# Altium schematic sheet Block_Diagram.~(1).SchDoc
size 431 x 279 mm; Date: Not shown in title block; ApprovedBy: Not shown in title block; CheckedBy: Not shown in title block; Author: Not shown in title block; CompanyName: Not shown in title block; Engineer: Not shown in title block; Organization: Not shown in title block; Address1: Not shown in title block; Address2: Not shown in title block; Address3: Not shown in title block; Address4: Not shown in title block; DocumentNumber: 1; Revision: Use project parameter SCH_Rev; SheetNumber: 1; SheetTotal: 4; PageSetup: Record=PageOptions¦CenterHorizontal=True¦CenterVertical=True¦PrintScale=1.00¦XCorrection=1.00¦YCorrection=1.00¦PrintKind=0¦BorderSize=5000000¦LeftOffset=0¦BottomOffset=0¦Orientation=2¦PaperLength=1000¦PaperWidth=1000¦Scale=100¦PaperSource=15¦PrintQuality=600¦MediaType=1¦DitherType=10¦PaperKind=Letter¦PrintScaleMode=1
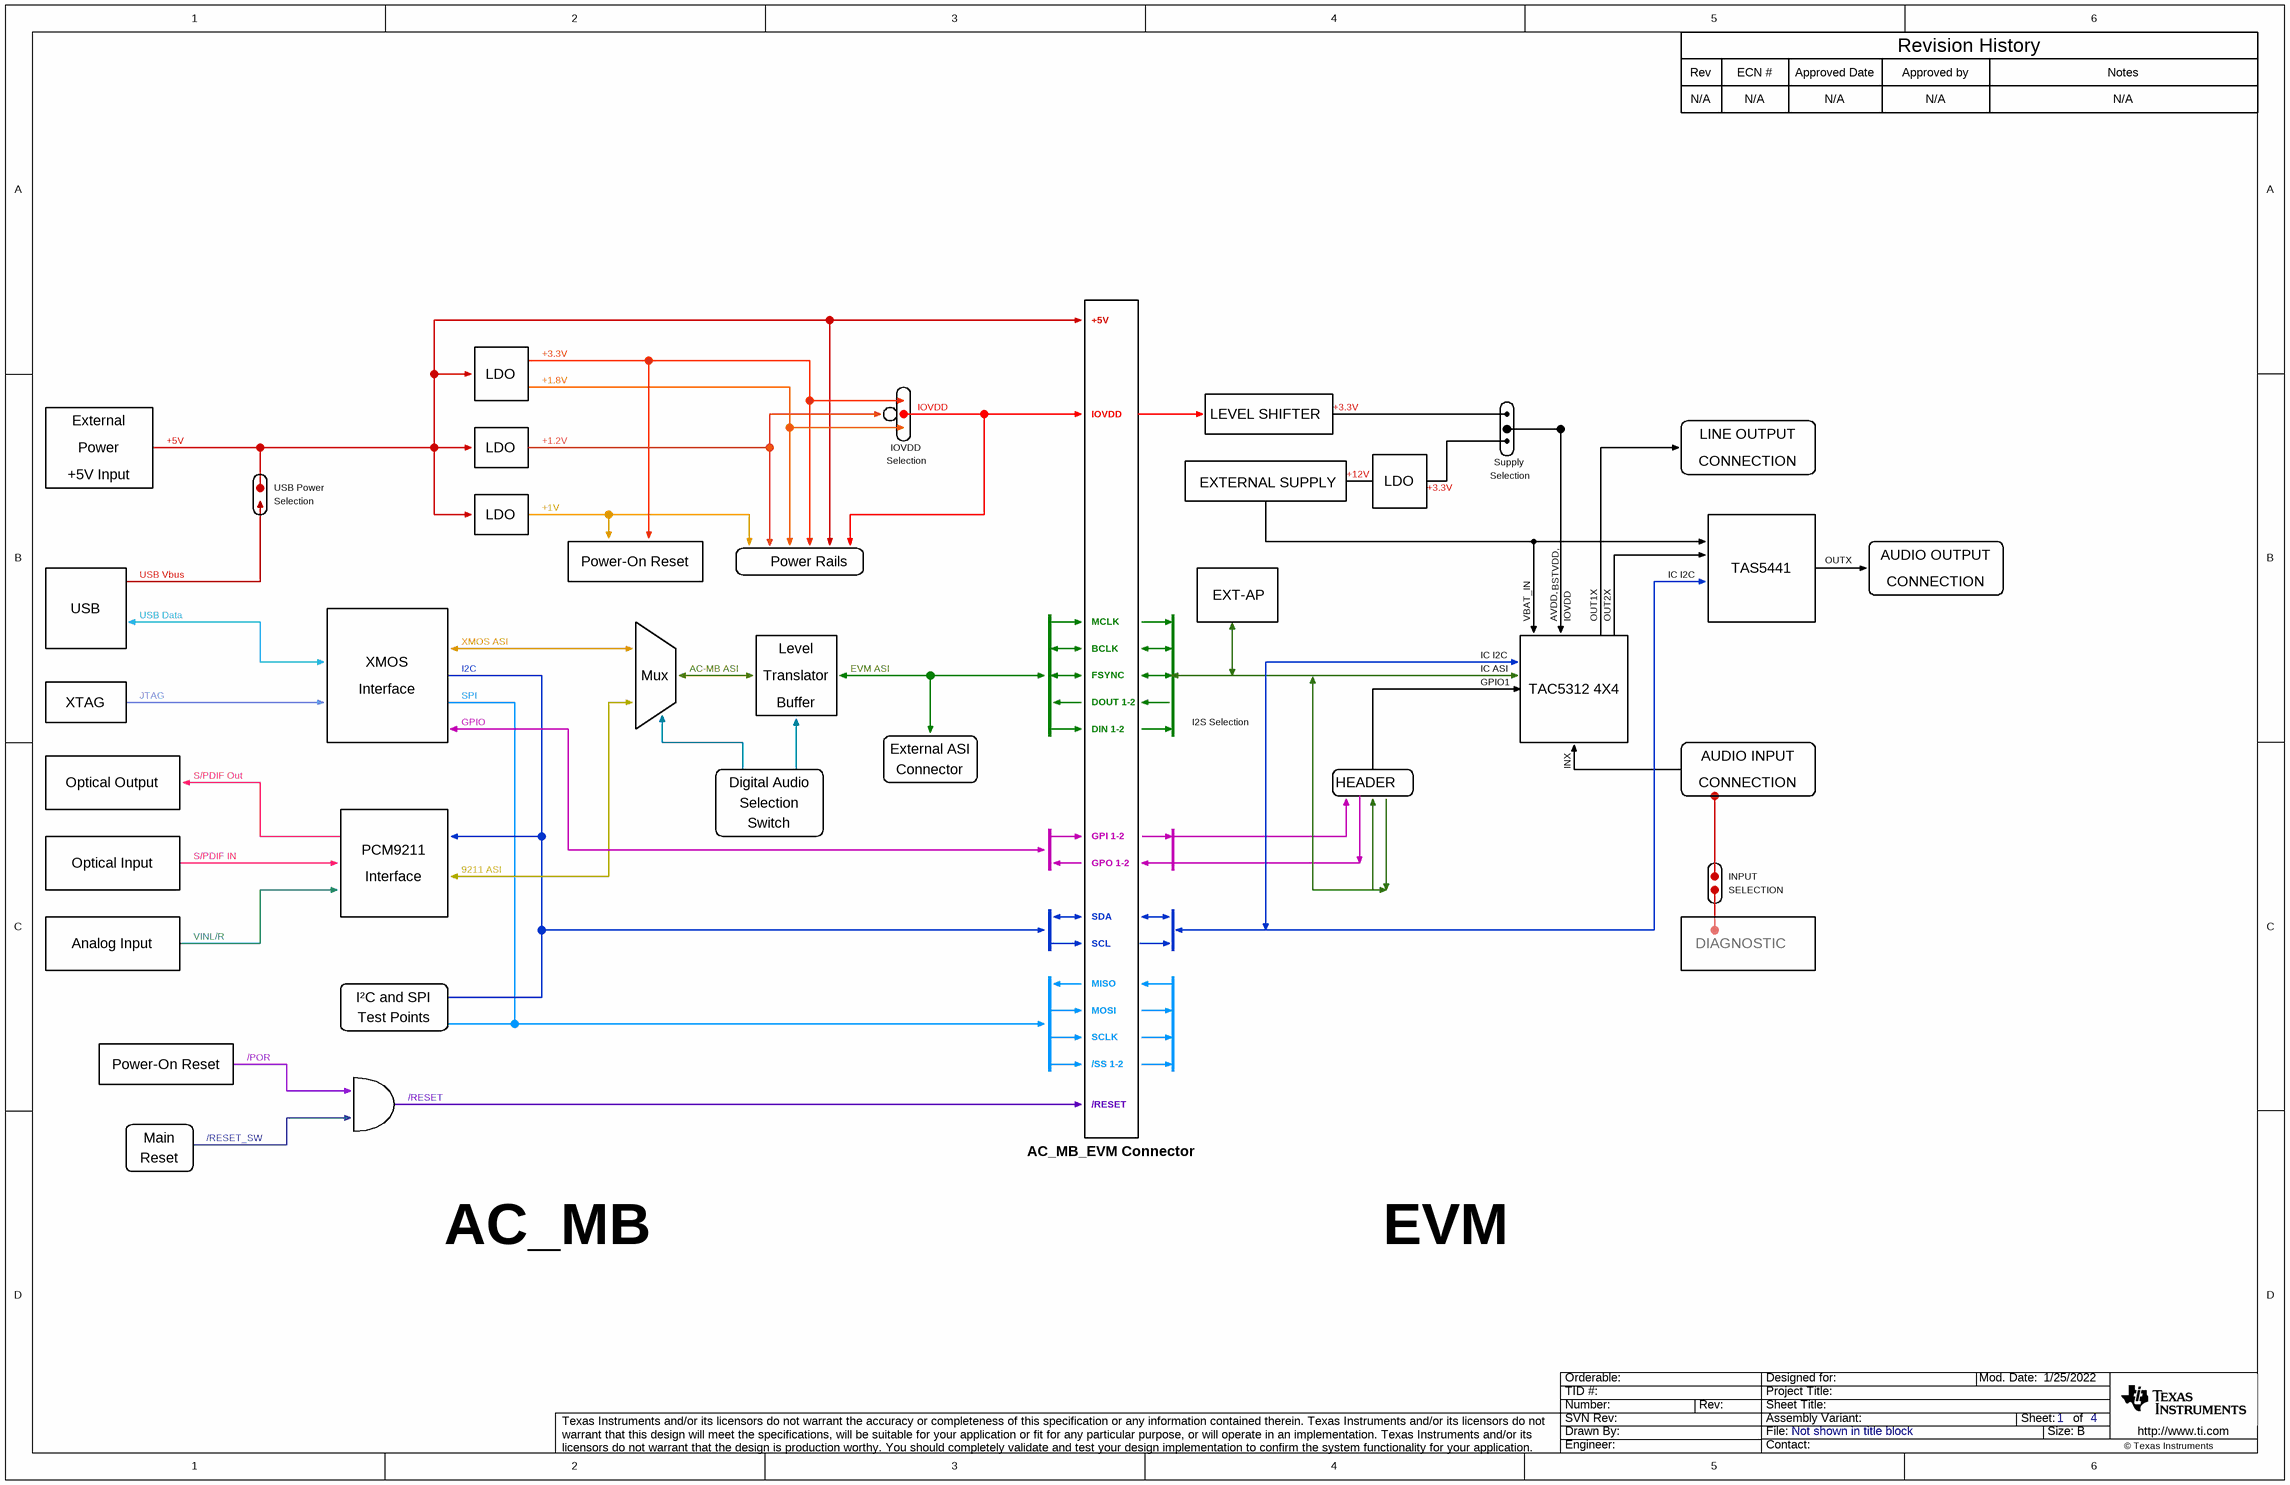
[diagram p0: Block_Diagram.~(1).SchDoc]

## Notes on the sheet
- Rev
- N/A
- ECN #
- Approved Date
- Approved by
- Revision History
- Notes
- +3.3V
- +5V
- External
- LDO
- +1.8V
- IOVDD
- LEVEL SHIFTER
- LINE OUTPUT
- +5V Input
- Power
- USB Power
- Selection
- +1.2V
- EXTERNAL SUPPLY
- +12V
- Supply
- CONNECTION
- +1V
- Power-On Reset
- Power Rails
- TAS5441
- OUTX
- AUDIO OUTPUT
- USB
- USB Data
- USB Vbus
- MCLK
- EXT-AP
- VBAT_IN
- BSTVDD,
- AVDD,
- OUT1X
- OUT2X
- IC I2C
- XTAG
- JTAG
- XMOS
- Interface
- SPI
- I2C
- XMOS ASI
- Mux
- AC-MB ASI
- Buffer
- Level
- Translator
- EVM ASI
- BCLK
- FSYNC
- DOUT 1-2
- IC ASI
- GPIO1
- TAC5312 4X4
- GPIO
- External ASI
- Connector
- DIN 1-2
- I2S Selection
- INX
- AUDIO INPUT
- Optical Output
- S/PDIF Out
- Digital Audio
- Switch
- GPI 1-2
- HEADER
- Optical Input
- S/PDIF IN
- PCM9211
- 9211 ASI
- GPO 1-2
- INPUT
- SELECTION
- Analog Input
- VINL/R
- SDA
- SCL
- DIAGNOSTIC
- I²C and SPI
- Test Points
- MISO
- MOSI
- SCLK
- /POR
- /RESET
- /SS 1-2
- Main
- Reset
- /RESET_SW
- AC_MB_EVM Connector
- AC_MB
- EVM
